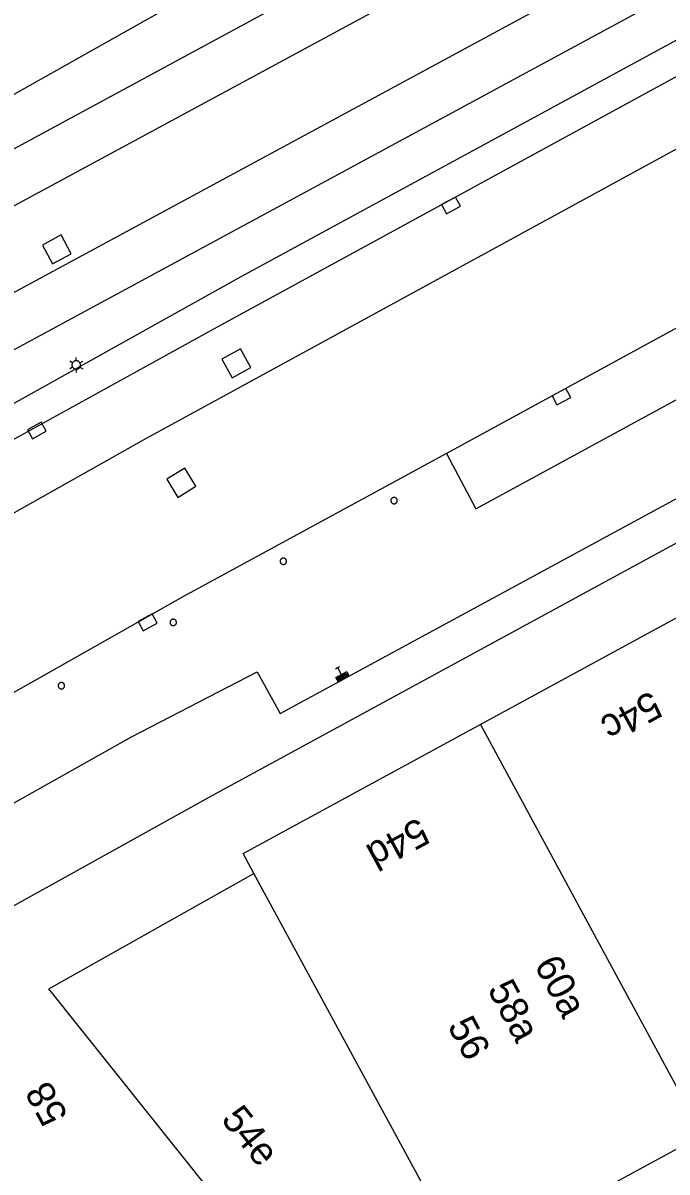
# Model space of a CAD drawing. Extents: x 81065 to 81486, y 452384 to 452681.
# Drawn here: x 81199.33 to 81217.68, y 452443.54 to 452476.31 of the extents above; entities that cross this region are included whole.
import ezdxf

# ---------------------------------------------------------------- set-up
doc = ezdxf.new("R2010")
doc.units = 0
for name, color, linetype in [('B-BH-AL-TOPOGRAFIE_HUISNUMMER-T25', 7, 'Continuous'), ('B-BH-IE-MEUBILAIR_WEGMEUBILAIR_LICHTMAST-S', 7, 'Continuous'), ('B-BH-IE-MEUBILAIR_WEGMEUBILAIR_PAAL-S', 7, 'Continuous'), ('B-BH-KL-DATA_CAI_KAST-S', 7, 'Continuous'), ('B-BH-OG-TOPOGRAFIE_BEBOUWING-GV', 7, 'Continuous'), ('B-BH-OG-TOPOGRAFIE_BEBOUWING_PANDSCHEIDING-GV', 7, 'Continuous'), ('B-BH-RI-GWA_RIOOLPUT-S', 7, 'Continuous'), ('B-BH-VH-KANTOPSLUITING-GV', 7, 'Continuous'), ('B-SB-OG-WEG_SPOOR_TRAM-G', 7, 'Continuous'), ('B-SRI-KOLK_COMBINATIE-S', 7, 'Continuous')]:
    doc.layers.add(name, color=color, linetype=linetype)

msp = doc.modelspace()

# ---------------------------------------------------------------- linework, layer by layer
at = {"layer": 'B-BH-IE-MEUBILAIR_WEGMEUBILAIR_LICHTMAST-S'}
for p, q in [((81200.848, 452466.677), (81200.848, 452466.769)), ((81200.742, 452466.616), (81200.663, 452466.662)), ((81200.742, 452466.494), (81200.663, 452466.448)), ((81200.848, 452466.433), (81200.848, 452466.341)), ((81200.953, 452466.616), (81201.033, 452466.662)), ((81200.953, 452466.494), (81201.033, 452466.448))]:
    msp.add_line(p, q, dxfattribs=at)
msp.add_lwpolyline([(81200.726, 452466.555), (81200.727, 452466.542), (81200.728, 452466.529), (81200.732, 452466.517), (81200.736, 452466.505), (81200.742, 452466.494), (81200.749, 452466.483), (81200.757, 452466.473), (81200.766, 452466.464), (81200.776, 452466.456), (81200.787, 452466.449), (81200.798, 452466.443), (81200.81, 452466.439), (81200.823, 452466.435), (81200.835, 452466.434), (81200.848, 452466.433), (81200.861, 452466.434), (81200.873, 452466.435), (81200.886, 452466.439), (81200.898, 452466.443), (81200.909, 452466.449), (81200.92, 452466.456), (81200.93, 452466.464), (81200.939, 452466.473), (81200.947, 452466.483), (81200.954, 452466.494), (81200.959, 452466.505), (81200.964, 452466.517), (81200.967, 452466.529), (81200.969, 452466.542), (81200.97, 452466.555), (81200.969, 452466.568), (81200.967, 452466.58), (81200.964, 452466.593), (81200.959, 452466.605), (81200.954, 452466.616), (81200.947, 452466.627), (81200.939, 452466.637), (81200.93, 452466.646), (81200.92, 452466.654), (81200.909, 452466.661), (81200.898, 452466.666), (81200.886, 452466.671), (81200.873, 452466.674), (81200.861, 452466.676), (81200.848, 452466.677), (81200.835, 452466.676), (81200.822, 452466.674), (81200.81, 452466.671), (81200.798, 452466.666), (81200.787, 452466.661), (81200.776, 452466.654), (81200.766, 452466.646), (81200.757, 452466.637), (81200.749, 452466.627), (81200.742, 452466.616), (81200.736, 452466.605), (81200.732, 452466.593), (81200.728, 452466.58), (81200.727, 452466.568), (81200.726, 452466.555)], dxfattribs=at)
at = {"layer": 'B-BH-IE-MEUBILAIR_WEGMEUBILAIR_PAAL-S'}
for points in [[(81209.812, 452462.687), (81209.813, 452462.677), (81209.814, 452462.668), (81209.817, 452462.658), (81209.82, 452462.649), (81209.824, 452462.641), (81209.83, 452462.633), (81209.836, 452462.625), (81209.842, 452462.619), (81209.85, 452462.613), (81209.858, 452462.607), (81209.867, 452462.603), (81209.875, 452462.6), (81209.885, 452462.597), (81209.894, 452462.596), (81209.904, 452462.595), (81209.913, 452462.596), (81209.923, 452462.597), (81209.932, 452462.6), (81209.941, 452462.603), (81209.95, 452462.607), (81209.958, 452462.613), (81209.965, 452462.619), (81209.972, 452462.625), (81209.978, 452462.633), (81209.983, 452462.641), (81209.987, 452462.649), (81209.991, 452462.658), (81209.993, 452462.668), (81209.995, 452462.677), (81209.995, 452462.687), (81209.995, 452462.696), (81209.993, 452462.706), (81209.991, 452462.715), (81209.987, 452462.724), (81209.983, 452462.732), (81209.978, 452462.74), (81209.972, 452462.748), (81209.965, 452462.755), (81209.958, 452462.761), (81209.95, 452462.766), (81209.941, 452462.77), (81209.932, 452462.774), (81209.923, 452462.776), (81209.913, 452462.778), (81209.904, 452462.778), (81209.894, 452462.778), (81209.885, 452462.776), (81209.875, 452462.774), (81209.867, 452462.77), (81209.858, 452462.766), (81209.85, 452462.761), (81209.842, 452462.755), (81209.836, 452462.748), (81209.83, 452462.74), (81209.824, 452462.732), (81209.82, 452462.724), (81209.817, 452462.715), (81209.814, 452462.706), (81209.813, 452462.696), (81209.812, 452462.687)], [(81206.658, 452460.957), (81206.659, 452460.947), (81206.66, 452460.938), (81206.663, 452460.928), (81206.666, 452460.919), (81206.67, 452460.911), (81206.676, 452460.903), (81206.682, 452460.895), (81206.688, 452460.889), (81206.696, 452460.883), (81206.704, 452460.877), (81206.713, 452460.873), (81206.721, 452460.87), (81206.731, 452460.867), (81206.74, 452460.866), (81206.75, 452460.865), (81206.759, 452460.866), (81206.769, 452460.867), (81206.778, 452460.87), (81206.787, 452460.873), (81206.796, 452460.877), (81206.804, 452460.883), (81206.811, 452460.889), (81206.818, 452460.895), (81206.824, 452460.903), (81206.829, 452460.911), (81206.833, 452460.919), (81206.837, 452460.928), (81206.839, 452460.938), (81206.841, 452460.947), (81206.841, 452460.957), (81206.841, 452460.966), (81206.839, 452460.976), (81206.837, 452460.985), (81206.833, 452460.994), (81206.829, 452461.002), (81206.824, 452461.01), (81206.818, 452461.018), (81206.811, 452461.025), (81206.804, 452461.031), (81206.796, 452461.036), (81206.787, 452461.04), (81206.778, 452461.044), (81206.769, 452461.046), (81206.759, 452461.048), (81206.75, 452461.048), (81206.74, 452461.048), (81206.731, 452461.046), (81206.721, 452461.044), (81206.713, 452461.04), (81206.704, 452461.036), (81206.696, 452461.031), (81206.688, 452461.025), (81206.682, 452461.018), (81206.676, 452461.01), (81206.67, 452461.002), (81206.666, 452460.994), (81206.663, 452460.985), (81206.66, 452460.976), (81206.659, 452460.966), (81206.658, 452460.957)], [(81203.521, 452459.214), (81203.522, 452459.204), (81203.523, 452459.195), (81203.526, 452459.185), (81203.529, 452459.176), (81203.533, 452459.168), (81203.539, 452459.16), (81203.545, 452459.152), (81203.551, 452459.146), (81203.559, 452459.14), (81203.567, 452459.134), (81203.576, 452459.13), (81203.584, 452459.127), (81203.594, 452459.124), (81203.603, 452459.123), (81203.613, 452459.122), (81203.622, 452459.123), (81203.632, 452459.124), (81203.641, 452459.127), (81203.65, 452459.13), (81203.659, 452459.134), (81203.667, 452459.14), (81203.674, 452459.146), (81203.681, 452459.152), (81203.687, 452459.16), (81203.692, 452459.168), (81203.696, 452459.176), (81203.7, 452459.185), (81203.702, 452459.195), (81203.704, 452459.204), (81203.704, 452459.214), (81203.704, 452459.223), (81203.702, 452459.233), (81203.7, 452459.242), (81203.696, 452459.251), (81203.692, 452459.259), (81203.687, 452459.267), (81203.681, 452459.275), (81203.674, 452459.282), (81203.667, 452459.288), (81203.659, 452459.293), (81203.65, 452459.297), (81203.641, 452459.301), (81203.632, 452459.303), (81203.622, 452459.305), (81203.613, 452459.305), (81203.603, 452459.305), (81203.594, 452459.303), (81203.584, 452459.301), (81203.576, 452459.297), (81203.567, 452459.293), (81203.559, 452459.288), (81203.551, 452459.282), (81203.545, 452459.275), (81203.539, 452459.267), (81203.533, 452459.259), (81203.529, 452459.251), (81203.526, 452459.242), (81203.523, 452459.233), (81203.522, 452459.223), (81203.521, 452459.214)], [(81200.334, 452457.408), (81200.335, 452457.398), (81200.336, 452457.389), (81200.339, 452457.379), (81200.342, 452457.37), (81200.346, 452457.362), (81200.352, 452457.354), (81200.358, 452457.346), (81200.364, 452457.34), (81200.372, 452457.334), (81200.38, 452457.328), (81200.389, 452457.324), (81200.397, 452457.321), (81200.407, 452457.318), (81200.416, 452457.317), (81200.426, 452457.316), (81200.435, 452457.317), (81200.445, 452457.318), (81200.454, 452457.321), (81200.463, 452457.324), (81200.472, 452457.328), (81200.48, 452457.334), (81200.487, 452457.34), (81200.494, 452457.346), (81200.5, 452457.354), (81200.505, 452457.362), (81200.509, 452457.37), (81200.513, 452457.379), (81200.515, 452457.389), (81200.517, 452457.398), (81200.517, 452457.408), (81200.517, 452457.417), (81200.515, 452457.427), (81200.513, 452457.436), (81200.509, 452457.445), (81200.505, 452457.453), (81200.5, 452457.461), (81200.494, 452457.469), (81200.487, 452457.476), (81200.48, 452457.482), (81200.472, 452457.487), (81200.463, 452457.491), (81200.454, 452457.495), (81200.445, 452457.497), (81200.435, 452457.499), (81200.426, 452457.499), (81200.416, 452457.499), (81200.407, 452457.497), (81200.397, 452457.495), (81200.389, 452457.491), (81200.38, 452457.487), (81200.372, 452457.482), (81200.364, 452457.476), (81200.358, 452457.469), (81200.352, 452457.461), (81200.346, 452457.453), (81200.342, 452457.445), (81200.339, 452457.436), (81200.336, 452457.427), (81200.335, 452457.417), (81200.334, 452457.408)]]:
    msp.add_lwpolyline(points, dxfattribs=at)
at = {"layer": 'B-BH-KL-DATA_CAI_KAST-S'}
for p, q in [((81208.231, 452457.893), (81208.352, 452457.959)), ((81208.292, 452457.927), (81208.4, 452457.727)), ((81208.246, 452457.643), (81208.554, 452457.811)), ((81208.318, 452457.513), (81208.246, 452457.643)), ((81208.275, 452457.63), (81208.55, 452457.78)), ((81208.322, 452457.543), (81208.275, 452457.63)), ((81208.303, 452457.618), (81208.546, 452457.75)), ((81208.327, 452457.574), (81208.303, 452457.618)), ((81208.626, 452457.68), (81208.318, 452457.513)), ((81208.322, 452457.543), (81208.597, 452457.693)), ((81208.327, 452457.574), (81208.57, 452457.706)), ((81208.331, 452457.604), (81208.542, 452457.72)), ((81208.546, 452457.75), (81208.57, 452457.706)), ((81208.55, 452457.78), (81208.597, 452457.693)), ((81208.554, 452457.811), (81208.626, 452457.68))]:
    msp.add_line(p, q, dxfattribs=at)
at = {"layer": 'B-BH-OG-TOPOGRAFIE_BEBOUWING-GV'}
msp.add_line((81237.578, 452472.168), (81204.716, 452454.266), dxfattribs=at)
for points in [[(81211.96, 452440.929), (81210.814, 452443.005), (81206.534, 452440.655), (81200.066, 452448.769), (81205.913, 452452.053), (81205.606, 452452.621), (81235.506, 452468.904), (81238.146, 452470.28), (81239.352, 452467.994), (81239.739, 452468.204)], [(81244.855, 452458.824), (81211.96, 452440.929)], [(81204.716, 452454.266), (81195.963, 452449.411), (81187.411, 452444.21), (81185.162, 452442.763)]]:
    msp.add_lwpolyline(points, dxfattribs=at)
at = {"layer": 'B-BH-OG-TOPOGRAFIE_BEBOUWING_PANDSCHEIDING-GV'}
for p, q in [((81212.37, 452456.305), (81218.695, 452444.593)), ((81210.814, 452443.005), (81205.913, 452452.053))]:
    msp.add_line(p, q, dxfattribs=at)
at = {"layer": 'B-BH-RI-GWA_RIOOLPUT-S'}
for p, q in [((81200.421, 452470.261), (81199.886, 452469.974)), ((81199.886, 452469.974), (81200.172, 452469.439)), ((81200.708, 452469.726), (81200.421, 452470.261)), ((81200.172, 452469.439), (81200.708, 452469.726)), ((81205.527, 452467.014), (81204.995, 452466.721)), ((81204.995, 452466.721), (81205.289, 452466.189)), ((81205.82, 452466.482), (81205.527, 452467.014)), ((81205.289, 452466.189), (81205.82, 452466.482)), ((81203.944, 452463.613), (81203.425, 452463.298)), ((81204.259, 452463.094), (81203.944, 452463.613)), ((81203.425, 452463.298), (81203.74, 452462.779)), ((81203.74, 452462.779), (81204.259, 452463.094))]:
    msp.add_line(p, q, dxfattribs=at)
at = {"layer": 'B-BH-VH-KANTOPSLUITING-GV'}
msp.add_line((81231.702, 452475.113), (81211.401, 452464.032), dxfattribs=at)
for points in [[(81220.335, 452486.293), (81217.165, 452484.447), (81214.437, 452482.941), (81207.347, 452478.935), (81194.35, 452471.616), (81162.041, 452453.42), (81156.047, 452449.726), (81150.272, 452445.697), (81149.556, 452445.135)], [(81166.505, 452441.653), (81172.172, 452445.873), (81172.7, 452446.254), (81172.867, 452446.35), (81180.693, 452451.592), (81188.735, 452456.496), (81192.385, 452458.571), (81202.855, 452464.464), (81237.7, 452483.516)], [(81162.668, 452442.441), (81169.895, 452447.714), (81170.064, 452447.811), (81171.72, 452449.007), (81177.948, 452453.188), (81182.8, 452456.219), (81191.033, 452460.983), (81205.552, 452469.075), (81226.775, 452480.625), (81229.065, 452481.856)], [(81228.003, 452478.214), (81227.178, 452479.831), (81204.778, 452467.581), (81194.026, 452461.655), (81191.474, 452460.18), (81186.357, 452457.208), (81179.07, 452452.739), (81171.84, 452447.862), (81171.561, 452447.682), (81164.068, 452442.154)], [(81211.401, 452464.032), (81212.229, 452462.449), (81232.11, 452473.274), (81231.498, 452474.442)], [(81186.938, 452440.997), (81186.918, 452441.056), (81185.937, 452443.2), (81185.347, 452444.153), (81191.344, 452447.929), (81190.629, 452449.149), (81194.948, 452451.753), (81202.427, 452455.953), (81205.999, 452457.801), (81206.662, 452456.613), (81223.822, 452465.932), (81237.064, 452473.144), (81239.739, 452468.204)], [(81211.401, 452464.032), (81203.884, 452459.947), (81192.147, 452453.296), (81184.931, 452448.995), (81183.907, 452448.346)]]:
    msp.add_lwpolyline(points, dxfattribs=at)
at = {"layer": 'B-SB-OG-WEG_SPOOR_TRAM-G'}
for p, q in [((81250, 452500.286), (81195.496, 452470.783)), ((81250, 452498.654), (81196.18, 452469.521)), ((81198.781, 452468.467), (81250, 452496.192)), ((81199.465, 452467.205), (81250, 452494.56))]:
    msp.add_line(p, q, dxfattribs=at)
msp.add_lwpolyline([(81176.342, 452454.198), (81177.765, 452455.05), (81179.189, 452455.901), (81180.616, 452456.742), (81182.05, 452457.572), (81183.487, 452458.398), (81184.928, 452459.217), (81186.372, 452460.031), (81187.818, 452460.84), (81189.268, 452461.645), (81190.72, 452462.446), (81192.174, 452463.244), (81193.63, 452464.039), (81195.087, 452464.832), (81196.545, 452465.624), (81199.465, 452467.205)], dxfattribs=at)
at = {"layer": 'B-SRI-KOLK_COMBINATIE-S'}
for p, q in [((81211.651, 452471.341), (81211.258, 452471.126)), ((81211.793, 452471.082), (81211.651, 452471.341)), ((81211.258, 452471.126), (81211.4, 452470.867)), ((81211.4, 452470.867), (81211.793, 452471.082)), ((81214.797, 452465.886), (81214.404, 452465.672)), ((81214.938, 452465.627), (81214.797, 452465.886)), ((81214.404, 452465.672), (81214.545, 452465.413)), ((81214.545, 452465.413), (81214.938, 452465.627)), ((81199.848, 452464.921), (81199.456, 452464.704)), ((81199.991, 452464.662), (81199.848, 452464.921)), ((81199.456, 452464.704), (81199.599, 452464.446)), ((81199.599, 452464.446), (81199.991, 452464.662)), ((81203.007, 452459.454), (81202.616, 452459.235)), ((81202.616, 452459.235), (81202.76, 452458.978)), ((81202.76, 452458.978), (81203.151, 452459.196)), ((81203.151, 452459.196), (81203.007, 452459.454))]:
    msp.add_line(p, q, dxfattribs=at)

# ---------------------------------------------------------------- texts
at = {"layer": 'B-BH-AL-TOPOGRAFIE_HUISNUMMER-T25'}
for s, rotation, p in [('54c', 208.5851, (81217.236, 452457.281)), ('54d', 208.5851, (81210.608, 452453.669)), ('60a', 298.3707, (81213.881, 452449.445)), ('58a', 298.3707, (81212.551, 452448.751)), ('56', 298.3707, (81211.411, 452447.706)), ('58', 118.3717, (81200.631, 452445.15)), ('54e', 308.7322, (81204.952, 452445.031))]:
    msp.add_text(s, height=0.8, rotation=rotation, dxfattribs=at).set_placement(p)

doc.saveas('drawing.dxf')
